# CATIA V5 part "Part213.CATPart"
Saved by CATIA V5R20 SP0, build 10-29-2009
Part number: FA 168700-2 comprimido
Revision: ANY
Definition: UNKNOWN
Nomenclature: FA 168700-2 comprimido
Source: Unknown
Bounding box of the stored display mesh (mm): x -2.8 to 2.8, y 0 to 4.04, z -2.8 to 2.8
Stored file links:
  C:\Users\Utente\Desktop\IO LAVORO\3D X SITO CF\CUMSA\3D files FA\FA 200700\Part213.CATPart
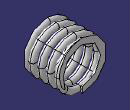
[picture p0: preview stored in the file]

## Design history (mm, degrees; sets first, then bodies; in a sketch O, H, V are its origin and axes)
Body1 "Cortar-Extruir1" (main body)
  Solid1: solid without history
